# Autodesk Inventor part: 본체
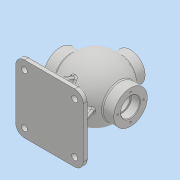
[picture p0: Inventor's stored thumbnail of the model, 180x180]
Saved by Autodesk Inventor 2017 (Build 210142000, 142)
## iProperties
Part Number: 본체
Material: 일반
Document SubType Name: Modeling
Designer: MRC
Density: 1 g/cm^3
Appearance: 기본값
Author: MRC
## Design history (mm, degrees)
sketch "스케치1"
  geometry: L1 (-65, 0)-(65, 0); L2 (65, 0)-(65, 31); L3 (65, 31)-(44.215, 31); L4 (-65, 0)-(-65, 31); L5 (-65, 31)-(-44.215, 31); A1 r 54 centre (0, 0) between (44.215, 31) and (-44.215, 31); A2 r 44 centre (0, 0) between (44, 0) and (-44, 0); 2 further points
  constraints: 10 end point, 4 point on circle, 3 coincident, 2 centre point, 2 horizontal, 2 vertical, 1 midpoint, 1 perpendicular
  dimensions: "d0" = 108 diameter of A1; "d1" = 88 diameter of A2; "d2" = 130 distance of L1.start L1.end; "d3" = 31 distance of L1.end L2.end; "d4" = 31 distance of L1.start L4.end
revolve "회전1" stored, may be unused: angle "d5" = 90 deg
sketch "스케치2"
  geometry: L1 (-44, 0)-(44, 0); A1 r 44 centre (0, 0) between (44, 0) and (-44, 0); 2 further points
  constraints: 2 end point, 2 point on circle, 1 centre point, 1 coincident, 1 horizontal, 1 midpoint
  dimensions: "d6" = 88 distance of L1.start L1.end; "d8" = 44 radius of A1
revolve "회전2" sketch "스케치2" stored, may be unused: angle "d9" = 90 deg
node "작업 평면1"
sketch "스케치3"
  geometry: C1 r 27 at (0, 0); 1 further point
  constraints: 1 centre point, 1 coincident
  dimensions: "d11" = 54 diameter of C1
extrude "돌출1" join sketch "스케치3" stored distance "d12" = 10; taper "d13" = 0 deg
hole "구멍1" diameter "d16" = 30; stored, may be unused: countersink angle "d20" = 90 deg, drill point angle "d22" = 0 deg; dims "d14" = 10, "d15" = 10, "d17" = 6, "d18" = 35, "d19" = 16, "d21" = 30
sketch "스케치4"
  geometry: C1 r 17.5 at (0, 0) reference; 1 further point
  constraints: 1 vertical alignment
  dimensions: "d23" = 24 distance of C1.centre point (0, 24)
hole "구멍2" sketch "스케치4" at (0, 24) diameter "d24" = 3.242; stored, may be unused: countersink angle "d28" = 90 deg, drill point angle "d30" = 118 deg; dims "d25" = 12, "d26" = 35, "d27" = 16, "d29" = 15
chamfer "모따기1" distance "d34" = 1; stored, may be unused: second distance "d35" = 2, angle "d36" = 45 deg
fillet "모깎기1" dims "d37" = 0.6
sketch "스케치5"
  geometry: C1 r 27 at (0, 0) reference; C2 r 13 at (0, 0)
  constraints: 1 centre point, 1 coincident
  dimensions: "d38" = 26 diameter of C2
extrude "돌출2" cut sketch "스케치5" distance "d39" = 25; taper "d40" = 0 deg
fillet "모깎기2" dims "d41" = 3
sketch "스케치6"
  geometry: C1 r 13 at (0, 0) reference; 1 further point
  constraints: 1 vertical alignment
  dimensions: "d42" = 20 distance of C1.centre point (0, -20)
hole "구멍3" sketch "스케치6" at (0, -20) diameter "d43" = 3.242; stored, may be unused: countersink angle "d47" = 90 deg, drill point angle "d49" = 118 deg; dims "d44" = 9, "d45" = 35, "d46" = 16, "d48" = 11
sketch "스케치7"
  geometry: L1 (-62.5, -75)-(62.5, -75); L2 (62.5, -75)-(62.5, -85); L3 (62.5, -85)-(-62.5, -85); L4 (-62.5, -85)-(-62.5, -75); 2 further points
  constraints: 8 end point, 2 parallel, 1 horizontal, 1 midpoint, 1 perpendicular, 1 vertical alignment
  dimensions: "d53" = 85 distance from line of L3 point (0, 0); "d54" = 10 distance of L1.end L2.end; "d55" = 125 distance of L2.end L3.end
extrude "돌출3" join sketch "스케치7" stored distance "d56" = 125; taper "d57" = 0 deg
fillet "모깎기3" dims "d58" = 16
fillet "모깎기4" dims "d59" = 16
sketch "스케치8"
  geometry: C1 r 5.5 at (0, 16); C2 r 5.5 at (0, 109); C3 r 5.5 at (93, 109); C4 r 5.5 at (93, 16); A1 r 16 centre (93, 109) between (109, 109) and (93, 125) reference; A2 r 16 centre (0, 109) between (0, 125) and (-16, 109) reference; A3 r 16 centre (0, 16) between (-16, 16) and (0, 0) reference; A4 r 16 centre (93, 16) between (93, 0) and (109, 16) reference; 1 further point
  constraints: 4 centre point, 4 coincident
  dimensions: "d60" = 11 diameter of C1; "d61" = 11 diameter of C2; "d62" = 11 diameter of C3; "d63" = 11 diameter of C4
extrude "돌출4" cut sketch "스케치8" distance "d64" = 125; taper "d65" = 0 deg
sketch "스케치10"
  geometry: L1 (93, 0)-(0, 0) reference; L2 (109, 16)-(109, 109) reference; L3 (42.5, 113)-(50.5, 113); L4 (50.5, 113)-(50.5, 12); L5 (50.5, 12)-(42.5, 12); L6 (42.5, 12)-(42.5, 113); L7 (42.5, 113)-(50.5, 12); L8 (50.5, 113)-(42.5, 12); L9 (-4, 66.5)-(97, 66.5); L10 (97, 66.5)-(97, 58.5); L11 (97, 58.5)-(-4, 58.5); L12 (-4, 58.5)-(-4, 66.5); L13 (-4, 66.5)-(97, 58.5); L14 (97, 66.5)-(-4, 58.5); 1 further point
  constraints: 24 end point, 4 midpoint, 4 parallel, 2 horizontal, 2 perpendicular
  dimensions: "d66" = 12 distance between parallel lines of L10 L2; "d67" = 12 distance between parallel lines of L1 L5; "d68" = 8 distance of L3.start L3.end; "d69" = 8 distance of L9.end L10.end
extrude "돌출5" join sketch "스케치10" stored distance "d70" = 125; taper "d71" = 0 deg
feature "면 기울기1" dims angle "d72" = 20 deg
fillet "모깎기5" dims "d73" = 3
fillet "모깎기6" dims "d74" = 3
node "작업 평면2"
sketch "스케치12"
  geometry: L1 (-27, 65)-(27, 65) reference; 2 further points
  constraints: 1 vertical alignment, 1 other
  dimensions: "d76" = 9 distance from line of L1 point (0, 56)
feature "엠보싱1" sketch "스케치12" dims "d77" = 0.5, "d78" = 0
chamfer "모따기2" distance "d79" = 1; stored, may be unused: second distance "d80" = 2, angle "d81" = 45 deg
node "솔리드1"
pattern_circular "원형 패턴1" dims angle "d32" = 360 deg
mirror "미러1"
pattern_circular "원형 패턴2" dims angle "d51" = 360 deg
other parameters: "d10" = 65
